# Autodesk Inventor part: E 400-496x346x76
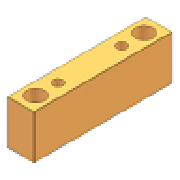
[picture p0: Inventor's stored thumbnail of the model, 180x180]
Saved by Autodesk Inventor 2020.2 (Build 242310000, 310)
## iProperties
IsCustomPart: 1
Manager: www.cadconsulting.pl
Company: Fabian Stasiak CAD Consulting
Created: 2014-02
Part Number: E 400-496x346x76
Material: S 55 C
Description: Spacer Block
Document SubType Name: Modeling
Designer: F.Stasiak
Standard Revision: 1
Manufacturer: DME
Language: pl-PL
Size Designation: 496x346x76
Categories: <MemberInstance><Categories><Category DisplayName="Forma wtryskowa" InternalName="349578f2-f4d4-4954-8c09-8e99297a61c0" Mnemonic="MOLD"><Category DisplayName="P
Density: 7.85 g/cm^3
Appearance: Orange (Pale)
Catalog Web Link: www.expertbooks.pl
Author: F.Stasiak
Subject: Zbiór ćwiczeń. Autodesk Inventor 2020. Kurs Professional
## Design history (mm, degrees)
sketch "Sketch1"
  geometry: L1 (-111, 248)-(-173, 248); L2 (-173, 248)-(-173, -248); L3 (-173, -248)-(-111, -248); L4 (-111, -248)-(-111, 248); L5 (173, 248)-(173, -248); L6 (111, -248)-(111, 248); L7 (111, 248)-(173, 248); L8 (111, -248)-(173, -248); 7 further points
  constraints: 16 end point, 3 parallel, 2 horizontal alignment, 2 midpoint, 2 perpendicular, 1 horizontal, 1 vertical
  dimensions: "d85" = 496 distance between parallel lines of L3 L1 (= L); "d86" = 62 distance between parallel lines of L4 L2 (= W_); "d88" = 62 distance between parallel lines of L5 L6 (= W_); "d89" = 173 distance from line of point (0, 0) L2 (= 0.5 x M_W); "d93" = 496 distance between parallel lines of L8 L7 (= L); "d94" = 173 distance from line of point (0, 0) L5 (= 0.5 x M_W); "d98" = 165 vertical distance of point (-137, 165) point (0, 0) (= 0.5 x S1_L); "d100" = 137 horizontal distance of point (-137, 165) point (0, 0) (= 0.5 x S1_W); "d101" = 137 horizontal distance of point (137, 165) point (0, 0) (= 0.5 x S1_W); "d102" = 165 vertical distance of point (0, 0) point (137, 165) (= 0.5 x S1_L); "d103" = 137 horizontal distance of point (-137, 208) point (0, 0) (= 0.5 x LS_W); "d105" = 208 vertical distance of point (-137, 208) point (0, 0) (= 0.5 x LS_L); "d106" = 137 horizontal distance of point (0, 0) point (137, 208) (= 0.5 x LS_W); "d107" = 208 vertical distance of point (137, 208) point (0, 0) (= 0.5 x LS_L)
extrude "Extrusion1" new body sketch "Sketch1" distance "d20" = 76 (= H_); taper "d30" = 0 deg
extrude "Extrusion2" join sketch "Sketch1" distance "d95" = 76 (= H_); taper "d96" = 0 deg
hole "Hole1" sketch "Sketch1" diameter "d129" = 18 (= S1_d1); stored, may be unused: countersink angle "d133" = 90 deg, drill point angle "d135" = 0 deg; dims "d130" = 6, "d131" = 4, "d132" = 2, "d134" = 76 (= H_)
pattern_linear "Rectangular Pattern1" dims "d156" = 330 (computed from S1_L, Ns)
hole "Hole2" sketch "Sketch1" diameter "d108" = 42 (= LS_d); stored, may be unused: countersink angle "d112" = 90 deg, drill point angle "d114" = 0 deg; dims "d109" = 6, "d110" = 4, "d111" = 2, "d113" = 76 (= H_)
pattern_linear "Rectangular Pattern2" dims "d138" = 416 (computed from LS_L, Nl)
hole "Hole3" sketch "Sketch1" diameter "d122" = 18 (= S1_d1); stored, may be unused: countersink angle "d126" = 90 deg, drill point angle "d128" = 0 deg; dims "d123" = 6, "d124" = 4, "d125" = 2, "d127" = 76 (= H_)
pattern_linear "Rectangular Pattern3" dims "d153" = 330 (computed from S1_L, Ns)
hole "Hole4" sketch "Sketch1" diameter "d115" = 42 (= LS_d); stored, may be unused: countersink angle "d119" = 90 deg, drill point angle "d121" = 0 deg; dims "d116" = 6, "d117" = 4, "d118" = 2, "d120" = 76 (= H_)
pattern_linear "Rectangular Pattern4" dims "d150" = 416 (computed from LS_L, Nl)
workplane "Work Plane1"
workplane "Work Plane2"
chamfer "Chamfer1" distance "d82" = 0.5; stored, may be unused: second distance "d83" = 2, angle "d84" = 45 deg
chamfer "Chamfer2" distance "d157" = 0.5; stored, may be unused: second distance "d158" = 2, angle "d159" = 45 deg
body "Solid1"
other parameters: "L" = 496 [user parameter; used in 2 equation terms], "W_" = 62 [user parameter; used in 2 equation terms], "H_" = 76 [user parameter; used in 7 equation terms], "M_W" = 346 [user parameter; used in 2 equation terms], "S1_W" = 274 [user parameter; used in 2 equation terms], "S1_d1" = 18 [user parameter; used in 2 equation terms], "LS_L" = 416 [user parameter; used in 4 equation terms], "LS_W" = 274 [user parameter; used in 2 equation terms], "LS_d" = 42 [user parameter; used in 2 equation terms], "d160" = 0, "d161" = 76 (= H_)
